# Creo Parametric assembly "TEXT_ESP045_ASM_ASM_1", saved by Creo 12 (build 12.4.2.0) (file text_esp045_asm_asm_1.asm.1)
Units: Custom; MM, KILOGRAM, SECS

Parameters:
  PTC_WM_ITERATION = "0"
  PTC_WM_VERSION = "-.0"
  PTC_WM_LIFECYCLE_STATE = "In Work"
  PTC_WM_LIFECYCLE = "MO_CADDocument"
  PTC_WM_CREATED_BY = "Maximilian Roepper (Z0017RMS: MO)"
  PTC_WM_CREATED_ON = "18-Sep-26 11:36:42 AM"
  PTC_WM_MODIFIED_BY = "Maximilian Roepper (Z0017RMS: MO)"
  PTC_WM_MODIFIED_ON = "18-Sep-26 11:36:46 AM"
  PDMLINKNUMBER = "PDM000071454901"
  PTC_WM_NUMBER = "PDM000071454901"

Other parameters: WEIGHT, WEIGHT_FACTOR, WEIGHT_ADD, MC_ERRORS, SUPPLIER

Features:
  1. coordinate system
  2. imported feature
  3. component "TEXT_ESP32_PRT_1"
  4. component "TEXT_ESP033_PRT_1"
  5. component "TEXT_ESP034_PRT_1"
  6. component "TEXT_ESP035_PRT_1"
  7. component "TEXT_ESP036_PRT_1"
  8. component "TEXT_ESP037_PRT_1"
  9. component "TEXT_ESP038_PRT_1"
  10. component "TEXT_ESP039_PRT_1"
  11. component "TEXT_ESP040_PRT_1"
  12. component "TEXT_ESP041_PRT_1"
  13. component "TEXT_ESP042_PRT_1"
  14. component "TEXT_ESP043_PRT_1"
  15. component "TEXT_ESP044_PRT_1"

Other named items: DRW_VIEW_ORG, ROUGH-GROB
